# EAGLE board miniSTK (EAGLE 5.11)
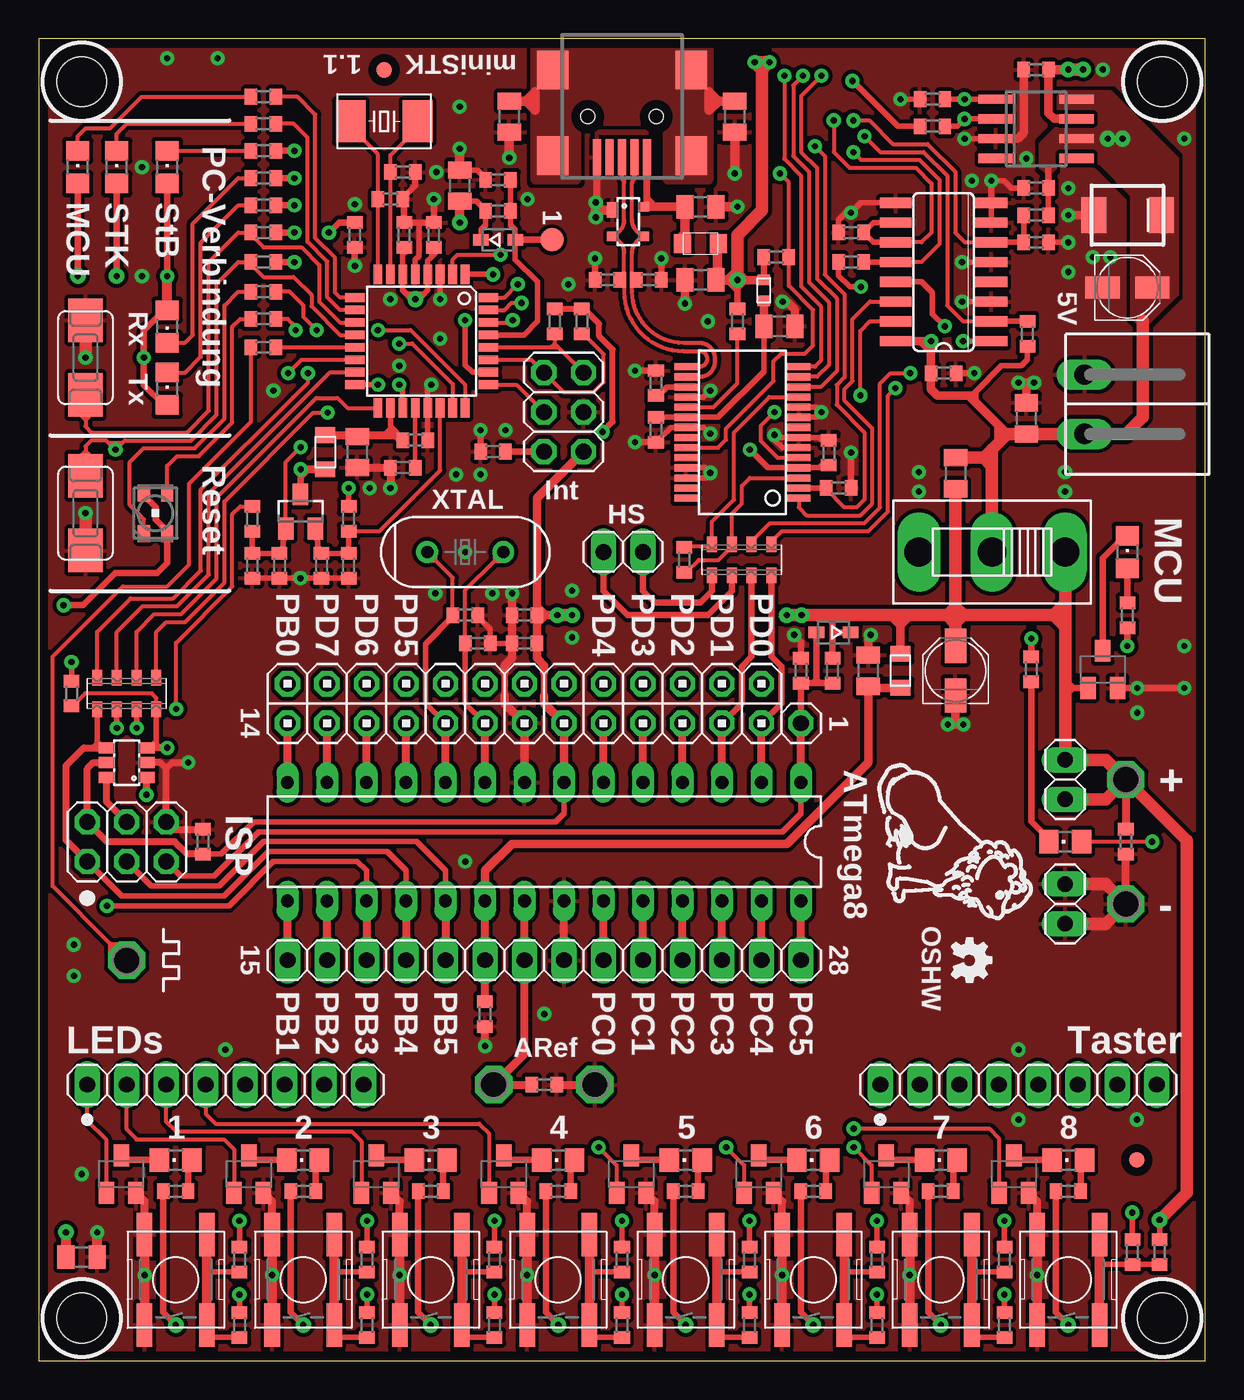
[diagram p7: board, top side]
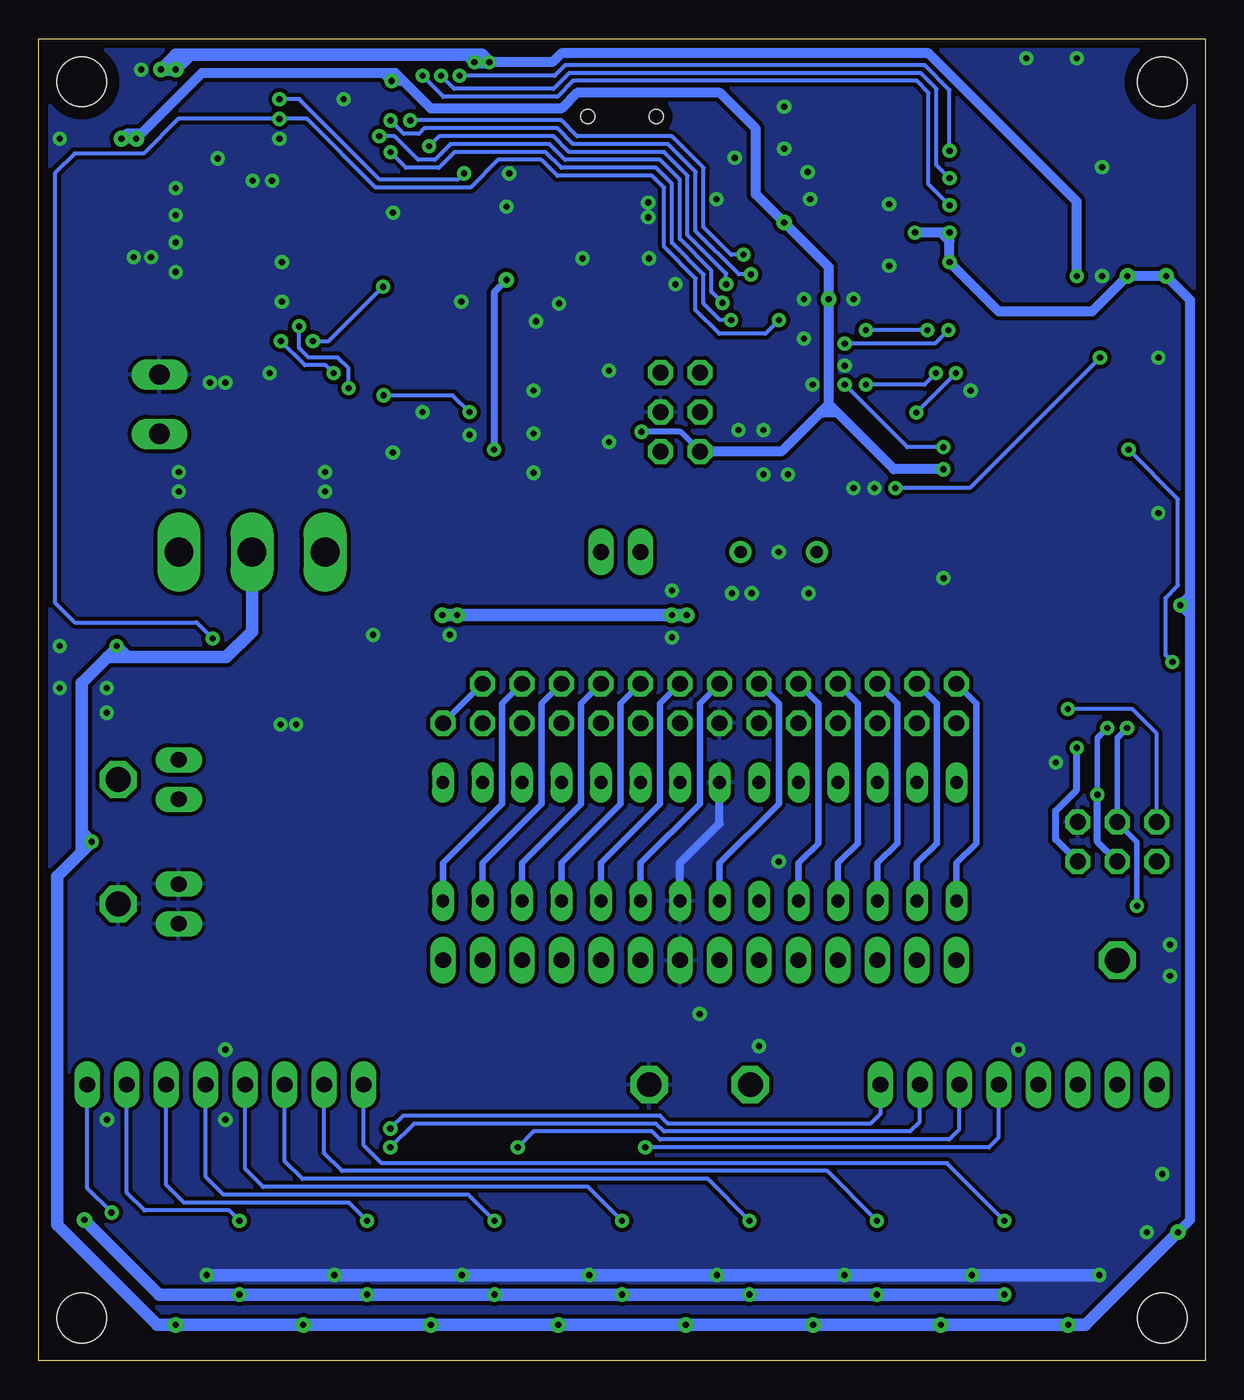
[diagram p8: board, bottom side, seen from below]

Size 75 x 85 mm. Coordinates in mm from the lower left corner, seen from the top.
Outline: 0,0 75,0 75,85 0,85 0,0
Copper layers (1*16): Top 0.035mm / dielectric 1.5mm / Bottom 0.035mm
Design rules "2-Layer 10x10 *": minimum track width 10mil, minimum drill 0.4mm, track to track 10mil, track to pad 10mil, pad to pad 10mil, via to via 10mil, smd to smd 10mil, copper to edge 0.6mm, drill to drill 10mil, minimum pad ring 12mil, minimum via ring 10mil, stop-mask expansion 4mil, vias tented up to drill 0.6mm, thermal gap 10mil
Net classes: 0 Standardleiter: width 0.254 mm, drill 0.4 mm; 1 USB Datenleitungen: width 0.254 mm; 2 IO-Schirm: clearance 0.5 mm; 3 Taktsignale: clearance 0.508 mm

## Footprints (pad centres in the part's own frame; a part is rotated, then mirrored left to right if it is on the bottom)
C-0603 = smd 0.8 x 1: 1 -0.8,0; 2 0.8,0
C-0805 = smd 1.1 x 1.5: 1 -1,0; 2 1,0
PANASONIC_B = smd 2.2 x 1.4: + 1.6,0; - -1.6,0
DIODE-SOD323 = smd 1 x 0.75: A 1.1,0; C -1.1,0
SOT23 = smd 1 x 1.4: 1 -0.95,-1.1; 2 0.95,-1.1; 3 0,1.1
SSOP28 = smd 0.46 x 1.5: 1 -4.225,-3.625; 2 -3.575,-3.625; 3 -2.925,-3.625; 4 -2.275,-3.625; 5 -1.625,-3.625; 6 -0.975,-3.625; 7 -0.325,-3.625; 8 0.325,-3.625; 9 0.975,-3.625; 10 1.625,-3.625; 11 2.275,-3.625; 12 2.925,-3.625; 13 3.575,-3.625; 14 4.225,-3.625; 15 4.225,3.625; 16 3.575,3.625; 17 2.925,3.625; 18 2.275,3.625; 19 1.625,3.625; 20 0.975,3.625; 21 0.325,3.625; 22 -0.325,3.625; 23 -0.975,3.625; 24 -1.625,3.625; 25 -2.275,3.625; 26 -2.925,3.625; 27 -3.575,3.625; 28 -4.225,3.625
SOIC8 = smd 0.6 x 2.2: 1 -1.905,-2.6; 2 -0.635,-2.6; 3 0.635,-2.6; 4 1.905,-2.6; 5 1.905,2.6; 6 0.635,2.6; 7 -0.635,2.6; 8 -1.905,2.6
SO16 = smd 0.66 x 2.032: 1 -4.445,-3.073; 2 -3.175,-3.073; 3 -1.905,-3.073; 4 -0.635,-3.073; 5 0.635,-3.073; 6 1.905,-3.073; 7 3.175,-3.073; 8 4.445,-3.073; 9 4.445,3.073; 10 3.175,3.073; 11 1.905,3.073; 12 0.635,3.073; 13 -0.635,3.073; 14 -1.905,3.073; 15 -3.175,3.073; 16 -4.445,3.073
TQFP32-08 = smd 1.27 x 0.559: 1 -4.293,2.8; 2 -4.293,2; 3 -4.293,1.2; 4 -4.293,0.4; 5 -4.293,-0.4; 6 -4.293,-1.2; 7 -4.293,-2; 8 -4.293,-2.8; 17 4.293,-2.8; 18 4.293,-2; 19 4.293,-1.2; 20 4.293,-0.4; 21 4.293,0.4; 22 4.293,1.2; 23 4.293,2; 24 4.293,2.8 | smd 0.559 x 1.27: 9 -2.8,-4.293; 10 -2,-4.293; 11 -1.2,-4.293; 12 -0.4,-4.293; 13 0.4,-4.293; 14 1.2,-4.293; 15 2,-4.293; 16 2.8,-4.293; 25 2.8,4.293; 26 2,4.293; 27 1.2,4.293; 28 0.4,4.293; 29 -0.4,4.293; 30 -1.2,4.293; 31 -2,4.293; 32 -2.8,4.293
1X02 = drill 1.016 long: 1 -1.27,0; 2 1.27,0
WE-CBF-0805 = smd 1.1 x 1.2: 1 -1.15,0; 2 1.15,0
BLM18 = smd 0.65 x 0.8: 1 -0.675,0; 2 0.675,0
BLM21 = smd 1 x 1.3: 1 -1.1,0; 2 1.1,0
CHIPLED-0805 = smd 1.25 x 1.5: A 1.05,0; C -1.05,0
OSRAM-TOPLED_2-S = smd 0.8 x 1.1: 1 -0.75,-1.3; 2 -0.75,1.3; 3 0.75,1.3; 4 0.75,-1.3
FIDUCIAL-1MM/CREAM = smd 1 x 1: FIDUCIAL 0,0
CRYSTAL-ABM7 = smd 1.9 x 2.7: 1 -2.15,0; 2 2.15,0
R-0603 = smd 0.8 x 1: 1 -0.8,0; 2 0.8,0
R-0805 = smd 1.1 x 1.5: 1 -1,0; 2 1,0
743C083 = smd 0.65 x 1: 1 -1.905,-1; 2 -0.635,-1; 3 0.635,-1; 4 1.905,-1; 5 1.905,1; 6 0.635,1; 7 -0.635,1; 8 -1.905,1
SWITCH-147873 = smd 2.8 x 2.2: P 2.4,0; S -2.4,0
TS-13-XX-X-C = drill 1.85 long: 1 -4.7,0; 2 0,0; 3 4.7,0
KSC-SW-J = smd 2.8 x 1: P1 -2.9,-2; P2 2.9,-2; S1 -2.9,2; S2 2.9,2
SC59-BEC = smd 1 x 1.4: B -0.95,-1.2; C 0,1.2; E 0.95,-1.2
TESTPOINT-1.6MM = drill 1.6 octagon: TP 0,0
TP15R = smd 1.5 x 1.5: TP 0,0
DO214-AA = smd 1.6 x 2.3: A 2.175,0; K -2.175,0
SOT143B = smd 1 x 0.7: 1 -0.75,-1 | smd 0.6 x 0.7: 2 0.95,-1; 3 0.95,1; 4 -0.95,1
SOT23-6_2 = smd 0.7 x 1: 1 -0.95,-1.3; 2 0,-1.3; 3 0.95,-1.3; 4 0.95,1.3; 5 0,1.3; 6 -0.95,1.3
MOUNT-DRILL_3.2 = hole 3.2: 0,0
31382102 = drill 1.3 long: 1 8,1.905; 2 8,-1.905
MINI-USB-B-SMD = smd 2.3 x 0.5: 1 7.85,1.6; 2 7.85,0.8; 3 7.85,0; 4 7.85,-0.8; 5 7.85,-1.6 | smd 2.5 x 2: S1 2.25,4.45; S2 7.75,4.45; S3 7.75,-4.45; S4 2.25,-4.45 | hole 0.9: 5.25,2.2; 5.25,-2.2
2X03 = drill 1.016 octagon: 1 -2.54,-1.27; 2 -2.54,1.27; 3 0,-1.27; 4 0,1.27; 5 2.54,-1.27; 6 2.54,1.27
1X01 = drill 1.016 octagon: 1 0,0
DIL28-3 = drill 0.813 long: 1 -16.51,-3.81; 2 -13.97,-3.81; 3 -11.43,-3.81; 4 -8.89,-3.81; 5 -6.35,-3.81; 6 -3.81,-3.81; 7 -1.27,-3.81; 8 1.27,-3.81; 9 3.81,-3.81; 10 6.35,-3.81; 11 8.89,-3.81; 12 11.43,-3.81; 13 13.97,-3.81; 14 16.51,-3.81; 15 16.51,3.81; 16 13.97,3.81; 17 11.43,3.81; 18 8.89,3.81; 19 6.35,3.81; 20 3.81,3.81; 21 1.27,3.81; 22 -1.27,3.81; 23 -3.81,3.81; 24 -6.35,3.81; 25 -8.89,3.81; 26 -11.43,3.81; 27 -13.97,3.81; 28 -16.51,3.81
1X14 = drill 1.016 long: 1 -16.51,0; 2 -13.97,0; 3 -11.43,0; 4 -8.89,0; 5 -6.35,0; 6 -3.81,0; 7 -1.27,0; 8 1.27,0; 9 3.81,0; 10 6.35,0; 11 8.89,0; 12 11.43,0; 13 13.97,0; 14 16.51,0
PQ_18_X = drill 0.8 round: 1 -2.45,0; 2 2.45,0
2X13 = drill 1.016 octagon: 1 -15.24,-1.27; 2 -15.24,1.27; 3 -12.7,-1.27; 4 -12.7,1.27; 5 -10.16,-1.27; 6 -10.16,1.27; 7 -7.62,-1.27; 8 -7.62,1.27; 9 -5.08,-1.27; 10 -5.08,1.27; 11 -2.54,-1.27; 12 -2.54,1.27; 13 0,-1.27; 14 0,1.27; 15 2.54,-1.27; 16 2.54,1.27; 17 5.08,-1.27; 18 5.08,1.27; 19 7.62,-1.27; 20 7.62,1.27; 21 10.16,-1.27; 22 10.16,1.27; 23 12.7,-1.27; 24 12.7,1.27; 25 15.24,-1.27; 26 15.24,1.27
1X08 = drill 1.016 long: 1 -8.89,0; 2 -6.35,0; 3 -3.81,0; 4 -1.27,0; 5 1.27,0; 6 3.81,0; 7 6.35,0; 8 8.89,0

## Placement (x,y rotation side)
C1  22pF  [C-0603]  28.22,46.13 0 top
C2  22pF  [C-0603]  27.42,47.94 0 top
C3  1µF  [C-0603]  10.56,33.37 90 top
C3.1  100nF  [C-0603]  58.18,63.5 0 top
C4  4,7µF  [C-0805]  53.34,44.37 90 top
C5  100nF  [C-0603]  31.23,46.13 180 top
C6  100nF  [C-0603]  28.69,22.29 270 top
C7  100nF  [C-0603]  32.5,17.75 0 top
C7.1  4,7µF  [C-0805]  2.75,6.67 0 top
C7.2  1µF  [C-0603]  69.9,33.37 270 top
C8  47nF  [C-0603]  49.01,44.37 90 top
C9  1µF  [C-0603]  20.32,72.39 270 top
C10  100nF  [C-0603]  39.69,59.87 270 top
C11  4,7µF  [C-0805]  27.07,75.56 90 top
C12  10nF  [C-0805]  42.55,74.2 0 top
C13  10nF  [C-0805]  30.25,80 270 top
C14  47pF  [C-0603]  39.23,69.5 0 top
C15  47pF  [C-0603]  36.57,69.5 180 top
C16  47nF  [C-0603]  29.53,75.93 180 top
C17  100nF  [C-0603]  39.69,62.87 90 top
C18  100nF  [C-0603]  50.8,58.39 90 top
C19  100nF  [C-0603]  64.14,83.03 180 top
C20  1µF  [C-0603]  64.14,75.41 180 top
C21  4,7µF  [C-0805]  42.55,69.5 180 top
C22  4,7µF  [C-0805]  47.62,66.52 0 top
C23  100nF  [C-0603]  23.41,57.42 180 top
C24  100nF  [C-0603]  23.5,72.39 90 top
C25  100nF  [C-0603]  25.4,72.39 90 top
C26  22pF  [C-0603]  23.41,76.44 0 top
C27  22pF  [C-0603]  22.61,74.69 0 top
C28  47nF  [C-0603]  18.18,51.12 270 top
C29  47nF  [C-0603]  15.48,51.12 270 top
C30  100nF  [C-0603]  24.21,59.2 0 top
C31  4,7µF  [C-0805]  20.48,58.42 270 top
C32  22µF  [PANASONIC_B]  58.95,44.37 90 top
C33  4,7µF  [C-0805]  63.5,60.59 90 top
C35  1µF  [C-0603]  31.23,47.94 180 top
C36  22µF  [PANASONIC_B]  70,69 0 top
C37  1µF  [C-0603]  29.21,58.46 180 top
D4.1  BAS16J  [DIODE-SOD323]  29.53,72.07 0 top
D4.2  BAT54C  [SOT23]  16.83,54.61 0 top
D6.1  BAS16J  [DIODE-SOD323]  51.11,46.83 180 top
IC2.1  FT232RL  [SSOP28]  45.24,59.69 90 top
IC2.2  MIC2025-2YM  [SOIC8]  64.14,79.22 270 top
IC3.1  74HC4053  [SO16]  58.18,70.01 90 top
IC4.1  ATmega88A-AU  [TQFP32-08]  24.61,65.56 270 top
JP1  RTS/CTS  [1X02]  37.58,52 0 top
L2.1  742792037  [WE-CBF-0805]  42.55,71.83 0 top
L2.2  BLM18PG121S  [BLM18]  46.62,68.83 90 top
L4.1  BLM21AH102S  [BLM21]  18.41,58.42 90 top
L6.1  BLM21AH102S  [BLM21]  55.4,44.37 270 top
LED7.1  LY R976  [CHIPLED-0805]  8.8,12.9 0 top
LED7.2  LY R976  [CHIPLED-0805]  17,12.9 0 top
LED7.3  LY R976  [CHIPLED-0805]  25.2,12.9 0 top
LED7.4  LY R976  [CHIPLED-0805]  33.4,12.9 0 top
LED7.5  LY R976  [CHIPLED-0805]  41.6,12.9 0 top
LED7.6  LY R976  [CHIPLED-0805]  49.8,12.9 0 top
LED7.7  LY R976  [CHIPLED-0805]  58,12.9 0 top
LED7.8  LY R976  [CHIPLED-0805]  66.2,12.9 0 top
LED9  LSG T676  [OSRAM-TOPLED_2-S]  7.5,54.5 0 top
LED10  LG R971  [CHIPLED-0805]  70,52 270 top
LED11  LG R971  [CHIPLED-0805]  2.5,76.75 270 top
LED12  LG R971  [CHIPLED-0805]  5,76.75 270 top
LED13  LS R976  [CHIPLED-0805]  8.25,76.75 270 top
LED14  LG R971  [CHIPLED-0805]  8.25,62.5 270 top
LED15  LG R971  [CHIPLED-0805]  8.25,66.5 90 top
LED16  LS R976  [CHIPLED-0805]  66,33.37 0 top
LOGO1.1  LOGO-10MM-TPLACE  [10MM-TPLACE]  59,33.37 270 top
LOGO1.2  OSHW-3MM-FILL-TSTOP  [OSHW-FILL-3MM-TSTOP]  57.75,36.25 90 bottom
LOGO1.3  OSHW-3MM-FILL-TPLACE  [OSHW-FILL-3MM-TPLACE]  60,25.75 270 top
MARK1  FIDUCIAL-1.0/CREAM  [FIDUCIAL-1MM/CREAM]  70.62,12.9 0 top
MARK2  FIDUCIAL-1.0/CREAM  [FIDUCIAL-1MM/CREAM]  22.21,83 0 top
P1.1  GF 4  [FOOT-12MM/REF]  7.5,73 0 top
P1.2  GF 4  [FOOT-12MM/REF]  67.5,73 0 top
P1.3  GF 4  [FOOT-12MM/REF]  12,7.5 0 top
P1.4  GF 4  [FOOT-12MM/REF]  63,7.5 0 top
Q4.1  14,7456MHz  [CRYSTAL-ABM7]  22.21,79.69 0 top
R1  330R  [R-0603]  12.9,6.5 270 top
R2  10k  [R-0603]  12.9,2.3 90 top
R3  330R  [R-0603]  21.1,6.5 270 top
R4  10k  [R-0603]  21.1,2.3 90 top
R5  330R  [R-0603]  29.3,6.5 270 top
R6  10k  [R-0603]  29.3,2.3 90 top
R7  330R  [R-0603]  37.5,6.5 270 top
R8  10k  [R-0603]  37.5,2.3 90 top
R9  330R  [R-0603]  45.7,6.5 270 top
R10  10k  [R-0603]  45.7,2.3 90 top
R11  330R  [R-0603]  53.9,6.5 270 top
R12  10k  [R-0603]  53.9,2.3 90 top
R13  330R  [R-0603]  62.1,6.5 270 top
R14  10k  [R-0603]  62.1,2.3 90 top
R15  330R  [R-0603]  70.33,6.99 270 top
R16  10k  [R-0603]  72.07,6.99 90 top
R17  330R  [R-0603]  8.8,10.9 180 top
R18  330R  [R-0603]  17,10.9 180 top
R19  330R  [R-0603]  25.2,10.9 180 top
R20  330R  [R-0603]  33.4,10.9 180 top
R21  330R  [R-0603]  41.6,10.9 180 top
R22  330R  [R-0603]  49.8,10.9 180 top
R23  330R  [R-0603]  58,10.9 180 top
R24  330R  [R-0603]  66.2,10.9 180 top
R25  10k  [R-0603]  51.04,44.37 90 top
R26  10k  [R-0603]  14.45,70.64 0 top
R27  1k  [R-0603]  44.93,66.83 90 top
R28  10k  [R-0603]  51.43,56.12 180 top
R29  1M  [R-0805]  44.75,80 270 top
R30  47k  [R-0603]  57.47,79.38 180 top
R31  10k  [R-0603]  47.42,70.96 180 top
R32  47k  [R-0603]  52.23,70.64 180 top
R33  47k  [R-0603]  63.58,66.03 270 top
R34  X  [R-0603]  64.14,73.66 0 top
R35  10k  [R-0603]  52.23,72.55 0 top
R36  10k  [R-0603]  14.45,72.55 0 top
R37  10k  [R-0603]  29.53,73.93 180 top
R38  X  [R-0805]  58.95,57.07 270 top
R39  X  [R-0603]  57.47,81.12 0 top
R40  47k  [R-0603]  19.92,54.13 90 top
R41  10k  [R-0603]  19.92,51.12 90 top
R42  10k  [R-0603]  13.73,51.12 90 top
R43  47k  [R-0603]  13.73,54.13 90 top
R44  47k  [R-0603]  34.92,66.83 90 top
R45  47k  [R-0603]  33.18,66.83 90 top
R46  330R  [R-0603]  70,47.94 270 top
R47  1,2k  [R-0603]  14.45,68.74 180 top
R48  560R  [R-0603]  14.45,66.99 180 top
R49  330R  [R-0603]  14.45,81.28 180 top
R50  330R  [R-0603]  14.45,79.53 180 top
R51  1,2k  [R-0603]  14.45,77.8 180 top
R52  330R  [R-0603]  14.45,74.3 180 top
R53  330R  [R-0603]  14.45,76.04 180 top
R54  1,2k  [R-0603]  63.82,44.45 270 top
R55  10k  [R-0603]  64.14,71.91 180 top
R56  X  [R-0603]  41.5,51.5 270 top
R57  47R  [R-0603]  14.45,65.16 180 top
R58  47R  [R-0603]  2.1,42.9 90 top
RN5.1  743C083271JP  [743C083]  45.2,51.5 0 top
RN5.2  743C083271JP  [743C083]  5.65,42.9 180 top
S5.1  147873-1  [SWITCH-147873]  3,54.5 270 top
S5.2  147873-1  [SWITCH-147873]  3,64.5 90 top
S6.1  TS-13-A12  [TS-13-XX-X-C]  61.3,52 180 top
S7.1  KSC222J  [KSC-SW-J]  8.8,5.2 270 top
S7.2  KSC222J  [KSC-SW-J]  17,5.2 270 top
S7.3  KSC222J  [KSC-SW-J]  25.2,5.2 270 top
S7.4  KSC222J  [KSC-SW-J]  33.4,5.2 270 top
S7.5  KSC222J  [KSC-SW-J]  41.6,5.2 270 top
S7.6  KSC222J  [KSC-SW-J]  49.8,5.2 270 top
S7.7  KSC222J  [KSC-SW-J]  58,5.2 270 top
S7.8  KSC222J  [KSC-SW-J]  66.2,5.2 270 top
T1  PDTC143ZT  [SC59-BEC]  5.3,12 0 top
T2  PDTC143ZT  [SC59-BEC]  13.5,12 0 top
T3  PDTC143ZT  [SC59-BEC]  21.7,12 0 top
T4  PDTC143ZT  [SC59-BEC]  29.9,12 0 top
T5  PDTC143ZT  [SC59-BEC]  38.1,12 0 top
T5.1  PDTC143ZT  [SC59-BEC]  68.42,44.45 0 top
T6  PDTC143ZT  [SC59-BEC]  46.3,12 0 top
T7  PDTC143ZT  [SC59-BEC]  54.5,12 0 top
T8  PDTC143ZT  [SC59-BEC]  62.7,12 0 top
TP1.1  5014  [TESTPOINT-1.6MM]  69.9,37.37 0 top
TP1.2  5011  [TESTPOINT-1.6MM]  69.9,29.37 0 top
TP1.3  5008  [TESTPOINT-1.6MM]  29.25,17.75 0 top
TP1.4  5006  [TESTPOINT-1.6MM]  35.75,17.75 0 top
TP1.5  5007  [TESTPOINT-1.6MM]  5.65,25.75 0 top
TP1.6  PTR1TP15R  [TP15R]  33,72.07 0 top
TVS1  SMBJ5V0A  [DO214-AA]  70.01,73.66 180 top
TVS2.1  PRTR5V0U2X  [SOT143B]  37.9,73.25 270 top
TVS5.1  SP3050-04HTG  [SOT23-6_2]  5.65,38.46 90 top
U$1  [MOUNT-DRILL_3.2]  2.75,2.75 0 top
U$2  [MOUNT-DRILL_3.2]  72.25,2.75 0 top
U$3  [MOUNT-DRILL_3.2]  72.25,82.25 0 top
U$4  [MOUNT-DRILL_3.2]  2.75,82.25 0 top
X1.1  31382102  [31382102]  75.25,61.5 180 top
X2.1  A-USBB-M5  [MINI-USB-B-SMD]  37.5,85.25 270 top
X5.1  Ext.  [2X03]  33.75,61 270 top
X6.1  Reset  [1X01]  49.01,40.99 0 top
X6.2  ATmega8  [DIL28-3]  32.5,33.37 180 top
X6.3  Ports  [1X14]  32.5,25.75 180 top
X6.4  ISP  [2X03]  5.65,33.37 0 top
X6.5  VCC  [1X02]  66,37.37 90 top
X6.6  GND  [1X02]  66,29.37 90 top
X6.7  PQ 18 G  [PQ_18_X]  27.42,52 180 top
X6.8  Ports  [2X13]  31.23,42.26 180 top
X7.1  Taster  [1X08]  63,17.75 0 top
X7.2  LEDs  [1X08]  12,17.75 0 top

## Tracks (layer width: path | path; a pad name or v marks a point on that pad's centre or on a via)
3V3OUT
  Top 0.356: IC2.1.17 40.39,62.62 39.84,62.06 C17.1
+5V  (via drill 0.4, 0.4 pad 1)
  Top 0.254: v71.6,33.37 LED16.A
  Top 0.356: 23.41,71.11 23.41,71.59 C24.1 | 23.41,71.11 IC4.1.6 23.41,68.83 23.65,68.58 | 23.41,71.11 23.65,71.36 | 25.24,70.96 25.72,71.44 | 25.24,70.96 25.01,70.73 IC4.1.4 25.01,68.83 24.44,68.26 v24.21,68.26 23.97,68.26 23.65,68.58 | 25.24,70.96 25.24,71.59 C25.1 | 23.65,68.58 24.77,68.58 | C11.1 28.15,74.56 28.73,73.98 R37.2 28.73,73.02 28.43,72.72 D4.1.C | R30.2 55.24,79.38 v52.32,82.3 | R34.2 C20.1 | R33.2 63.58,64.37 63.18,63.98 61.91,63.98 60.25,62.31 | 60.25,62.07 60.25,62.31 | 60.25,62.07 60.25,61.67 | 60.25,62.31 60.01,62.07 | 60.09,62.07 60.25,62.07 | R32.2 51.43,69.78 52.15,69.06 v52.86,69.06
  Top 0.381: R45.2 R44.2 35.08,67.63 36.04,66.67 36.04,65.88 36.89,65.02 36.89,60.37 v36.25,59.73
  Top 0.406: R17.2 8,3.1 v8.8,2.3 | R18.2 16.2,3.1 v17,2.3 | R19.2 24.4,3.1 v25.2,2.3 | R20.2 32.6,3.1 v33.4,2.3 | R21.2 40.8,3.1 v41.6,2.3 | R22.2 49,3.1 v49.8,2.3 | R23.2 57.2,3.1 v58,2.3 | R24.2 65.4,3.1 v66.2,2.3 | v5,69.75 LED12.A | v2.5,69.75 LED11.A | v16.43,72.55 R36.2 | v16.43,70.64 R26.2 | LED9.2 6.75,55.63 7.5,54.88 7.5,54.08 8.25,53.33 LED9.4 8.25,51.28 7.61,50.64 4.92,50.64 2.86,48.58 v1.59,48.58 | D4.2.3 16.83,56.83 | 16.83,56.83 v16.83,57.32 | 16.83,56.83 17.3,57.31 | v70,45.96 R46.2 | X5.1.5 C37.1 | C20.1 64.94,76.68 | C9.1 19.29,73.19 v18.65,72.55
  Top 0.508: v16.83,57.32 L4.1.1
  Top 0.559: 56.75,65.56 IC3.1.16 | 56.75,65.56 v57.38,65.56 57.38,64.94 | 57.38,64.94 C3.1.1 57.38,62.47 57.78,62.07 59.82,62.07 | 57.38,64.94 56.75,65.56 | 62.29,59.59 61.71,60.18 | 61.71,60.18 61.71,59.25 | 61.71,60.18 59.82,62.07 | 59.82,62.07 60.09,62.07
  Top 0.61: v27.07,73.18 C11.1
  Top 0.635: C7.1.1 v1.75,8.26
  Top 0.813: 71,66.87 71,60.68 69.91,59.59 X1.1.1 C33.1 62.29,59.59 61.3,58.6 | S6.1.2 61.3,57.53 | 61.3,57.53 61.3,58.6 | 61.3,58.6 60.77,58.07 | 60.77,58.07 R38.1 | 61.3,57.53 60.77,58.07
  Bottom 0.254: v52.86,69.06 56.36,65.56 v57.38,65.56
  Bottom 0.381: X5.1.5 33.75,59.73 v36.25,59.73
  Bottom 0.635: v16.83,57.32 20.01,57.32 23.65,60.96 | 23.65,60.96 24.21,61.51 | 24.21,61.51 v24.21,68.26 24.21,70.32 v27.07,73.18 28.89,75.01 28.89,79.22 31.21,81.53 40.39,81.53 41.4,80.52 49.78,80.52 52.07,82.8 52.83,82.8 | 16.43,71.99 v16.43,72.55 v18.65,72.55 | 0.95,49.21 0.95,68.2 v2.5,69.75 v5,69.75 7.28,67.47 13.26,67.47 v16.43,70.64 16.43,71.99 | 0.95,49.21 v1.59,48.58 0.95,47.94 | 0.95,47.94 0.95,49.21 | 0.95,47.94 0.95,9.05 v1.75,8.26 | 16.43,71.99 16.99,72.55 | 24.21,61.51 24.68,61.04 | 24.68,61.04 27.26,58.46 X5.1.5 | 24.68,61.04 24.59,60.96 23.65,60.96 | 51.56,82.3 v52.32,82.3 52.83,82.8 | 52.83,82.8 64.52,82.8 68.42,78.9 | 68.42,78.9 v68.74,78.58 v69.69,78.58 69.37,78.9 68.42,78.9
  Bottom 0.813: v1.75,8.26 7.7,2.3 v8.8,2.3 v17,2.3 v25.2,2.3 v33.4,2.3 v41.6,2.3 v49.8,2.3 v58,2.3 v66.2,2.3 67.39,2.3 73.82,8.73 73.82,31.15 v71.6,33.37 72.23,34.01 | 72.23,34.01 72.23,32.77 | 72.23,34.01 72.23,43.59 70.58,45.24 | 70.58,45.24 62.95,45.24 61.3,46.9 S6.1.2 | 70.58,45.24 70,45.82 v70,45.96 69.29,45.24
  pour Top (no thermals): 65.88,81.6 68.9,81.6 73.18,77.31 73.18,68.58 71.28,66.68 70.72,66.68 70.33,67.07 70.33,74.93 68.26,76.99 65.64,76.99 65.01,76.36 64.85,76.36 64.45,76.76 64.45,78.26 65.56,79.38 65.56,81.28
GND  (via drill 0.4)
  Top 0.356: C5.2 C1.2 29.02,47.05 28.22,47.84 C2.2 | 50.17,59.37 50.8,59.37 C18.2 | 50.17,59.37 IC2.1.7 47.47,59.37 v47.31,59.53 47.31,59.21 47.81,58.72 IC2.1.6 | 50.17,59.37 50.48,59.05 | IC4.1.5 24.21,70.8 24.45,71.04 24.45,73.19 | v25.81,68.26 IC4.1.3 | R41.1 C28.2 v16.82,50.32 C29.2 R42.1 | C30.2 IC4.1.21 25.01,62.53 v25.24,62.76 | C16.2 28.73,76.05 28.21,76.56 C11.2 | IC2.1.18 42.76,61.97 v43.18,62.39 | v43.18,59.61 42.78,60.02 IC2.1.21 40.65,60.02 C10.2 | IC2.1.25 42.85,57.41 v43.18,57.09 42.85,56.77 IC2.1.26 | IC2.1.10 50,61.31 v50.32,60.99 50,60.66 IC2.1.9 | v55.4,81.12 R39.1 | v59.37,70.64 IC3.1.5 | v59.37,68.1 IC3.1.3 | v59.53,78.58 IC2.2.3 | IC3.1.9 52.86,74.45 v52.23,73.82 51.91,73.82 51.43,73.34 R35.1 | R55.1 v66.2,71.91 | IC3.1.7 IC3.1.8 | C20.2 62.55,75.41 62.07,75.88 v61.26,75.88
  Top 0.406: C26.2 24.21,75.56 23.41,74.76 C27.2 23.5,74.69 C24.2 24.45,73.19 C25.2 v25.4,74.69 | C15.2 v35.77,70.88 | C14.2 v40.03,70.88 | T5.1.E v70.64,43.25 v73.66,43.25 | v20.32,70.41 C9.2 | C37.2 v28.41,59.85 | C10.2 v38.34,59.06 | C17.2 v38.34,63.66 | IC3.1.8 v61.26,75.88 | C3.1.2 v60.17,63.5 | R28.1 v52.23,58.39 | 29.96,42.78 29.96,44.28 | C8.2 49.01,46.24 v48.58,46.67
  Top 0.457: C3.2 8.66,34.17 X6.4.6 8.19,38.08 | TVS5.1.2 7.81,38.46 8.19,38.08 | X2.1.5 35.9,74.56 v35.81,74.48 | 8.19,38.08 8.57,38.46 v9.6,38.46
  Top 0.508: S7.8.P1 64.2,10.25 T8.E | S7.7.P1 56,10.25 T7.E | S7.6.P1 47.8,10.25 T6.E | S7.5.P1 39.6,10.25 T5.E | S7.4.P1 31.4,10.25 T4.E | S7.3.P1 23.2,10.25 T3.E | S7.2.P1 15,10.25 T2.E | S7.1.P1 6.8,10.25 T1.E | X6.3.7 X6.2.22 | C31.2 C23.2 v22.61,56.12 | TP1.2.TP C7.2.2 | C7.2 TP1.4.TP | v28.69,20.23 C6.2
  Top 0.559: v30.43,49.35 C35.2 C5.2 30.43,45.17 29.96,44.7 29.96,44.28 | v63,62.9 63.5,62.9 | 63.5,62.9 v64,62.9 | 58.95,40.92 v59.45,40.92 | 58.95,40.92 v58.45,40.92 | C19.2 63.34,78.96 62.95,78.58 IC2.2.3 | v41.55,67.98 C21.2 | C22.2 48.62,67.58 48.1,68.1 v47.83,68.1 | TVS1.A v66.2,73.66 | 63.5,62.9 C33.2 | C32.- 58.95,40.92 | 29.96,42.78 29.96,42.26 X6.8.14 X6.2.8 | C4.2 53.34,46.51 v53.5,46.67
  Top 0.61: S7.1.P2 v6.8,5.5 S7.1.P1 | S7.2.P2 v15,5.5 S7.2.P1 | S7.3.P2 v23.2,5.5 S7.3.P1 | S7.4.P2 v31.4,5.5 S7.4.P1 | S7.5.P2 v39.6,5.5 S7.5.P1 | S7.6.P2 v47.8,5.5 S7.6.P1 | S7.7.P2 v56,5.5 S7.7.P1 | S7.8.P2 v64.2,5.5 S7.8.P1 | v30.25,77.35 C13.2 | v44.75,76.35 R29.2 | 35.81,74 TVS2.1.1 | v35.81,73.52 35.81,74 | 35.81,74 v35.81,74.48 | C12.2 v44.93,74.2 | C11.2 v27.07,77.95
  Top 0.635: C7.1.2 v3.75,8.26
  Top 0.813: v3,64.5 S5.2.P | S5.1.P v3,54.5 | X6.6.2 68.63,30.64 TP1.2.TP 68.63,28.1 X6.6.1
  Bottom 0.508: X6.2.22 33.77,32 31.23,34.54 X6.2.8
  Bottom 0.813: v6.8,5.5 v15,5.5 v23.2,5.5 v31.4,5.5 v39.6,5.5 v47.8,5.5 v56,5.5 v64.2,5.5
  other vias: 21.27,56.12 31.42,74.69 22.61,68.26 23.18,63.98 6.62,69.75 27.42,52 6.62,76.75 15.08,62.39 2.75,12 8.25,83.75 11.5,83.75 27.07,80.64 20.32,74.37 25.56,76.44 27.42,32.09 32.5,22.29 28.41,56.99 26.83,56.99 30,59.85 43.02,66.83 34.29,49.53 2.25,26.75 2.25,24.75 56.6,55.88 66,55.88 66.2,75.41 68.42,83.03 67.79,70.96 68.9,70.96 73.66,45.95 66.2,70.01 70.64,41.66 66,57.15 56.6,57.15 34.29,46.51 60.01,75.88 63.5,77.31 25.81,65.72 34.05,69.22 70.62,15.5 63,15.5 63,20 12,20 29.16,49.35 25.5,49.35 73.66,78.58
  pour Bottom (rank 6): 0,85 75,85 75,0 0,0
  pour Top (rank 6): 0,85 75,85 75,0 0,0
  pour Top (rank 2, no thermals): 69.85,74.77 69.85,68.26 69.53,67.95 67.15,67.95 66.83,68.26 66.83,74.77 67.15,75.09 69.53,75.09
GNDIO
  Top 0.61: C13.1 31.31,81 | 31.31,81 31.91,81.6 31.91,80.41 31.32,81 31.31,81 | 43.7,81 R29.1 | 43.7,81 43.1,81.6 43.1,80.41 43.69,81 43.7,81
  pour Top (no thermals): 31.75,85 43.25,85 43.25,76 arc-90 43,75.75 40.5,75.75 arc-90 40.25,76 40.25,79.5 34.75,79.5 34.75,76 arc-90 34.5,75.75 32,75.75 arc-90 31.75,76
IC2.1/!RESET
  Top 0.254: IC2.1.19 43.38,61.31 44.93,62.87 R27.1
N$1
  Top 0.356: R16.1 R15.2 68.2,6.18 68.2,6.19
  Top 0.61: S7.8.S2 68.2,6.19 S7.8.S1
N$2
  Top 0.356: R14.1 60,1.5 S7.7.S2 | R13.2 60,5.7 60,6.35
  Top 0.61: S7.7.S2 60,6.35 S7.7.S1
N$3
  Top 0.356: R12.1 51.8,1.5 S7.6.S2 | R11.2 51.8,5.7 51.8,6.35
  Top 0.61: S7.6.S2 51.8,6.35 S7.6.S1
N$4
  Top 0.356: R10.1 43.6,1.5 S7.5.S2 | R9.2 43.6,5.7 43.6,6.35
  Top 0.61: S7.5.S2 43.6,6.35 S7.5.S1
N$5
  Top 0.356: R8.1 35.4,1.5 S7.4.S2 | R7.2 35.4,5.7 35.4,6.35
  Top 0.61: S7.4.S2 35.4,6.35 S7.4.S1
N$6
  Top 0.356: R6.1 27.2,1.5 S7.3.S2 | R5.2 27.2,5.7 27.2,6.35
  Top 0.61: S7.3.S2 27.2,6.35 S7.3.S1
N$7
  Top 0.356: R4.1 19,1.5 S7.2.S2 | R3.2 19,5.7 19,6.35
  Top 0.61: S7.2.S2 19,6.35 S7.2.S1
N$8
  Top 0.356: R2.1 10.8,1.5 S7.1.S2 | R1.2 10.8,5.7 10.8,6.35
  Top 0.61: S7.1.S2 10.8,6.35 S7.1.S1
N$9
  Top 0.406: R17.1 9.6,12.9 LED7.1.A
N$10
  Top 0.406: R18.1 17.8,12.9 LED7.2.A
N$11
  Top 0.406: R19.1 26,12.9 LED7.3.A
N$12
  Top 0.406: R20.1 34.2,12.9 LED7.4.A
N$13
  Top 0.406: R21.1 42.4,12.9 LED7.5.A
N$14
  Top 0.406: R22.1 50.6,12.9 LED7.6.A
N$15
  Top 0.406: R23.1 58.8,12.9 LED7.7.A
N$16
  Top 0.406: R24.1 67,12.9 LED7.8.A
N$17
  Top 0.406: LED7.8.C 62.7,12.9 T8.C
N$18
  Top 0.406: LED7.7.C 54.5,12.9 T7.C
N$19
  Top 0.406: LED7.6.C 46.3,12.9 T6.C
N$20
  Top 0.406: LED7.5.C 38.1,12.9 T5.C
N$21
  Top 0.406: LED7.4.C 29.9,12.9 T4.C
N$22
  Top 0.406: LED7.3.C 21.7,12.9 T3.C
N$23
  Top 0.406: LED7.2.C 13.5,12.9 T2.C
N$24
  Top 0.406: LED7.1.C 5.3,12.9 T1.C
N$25
  Top 0.457: 39.1,74.72 39.1,74.2 TVS2.1.4 | 39.1,74.72 X2.1.1 | 39.1,74.72 39.53,74.3
  Top 0.559: C12.1 TVS2.1.4
  Top 0.61: L2.1.1 41.55,71.83 41.55,72.5 | C12.1 41.55,72.53 41.55,72.5 | 41.55,72.5 41.2,72.15
N$28
  Top 0.254: IC4.1.7 C26.1 22.61,77.53 24.36,79.28 Q4.1.2
N$29
  Top 0.305: C23.1 IC4.1.20
N$30
  Top 0.254: IC4.1.8 C27.1 21.81,77.57 20.06,79.32 Q4.1.1
N$31
  Top 0.406: T5.1.C 68.42,51.62 69.85,53.05 LED10.C
N$32
  Top 0.406: R46.1 LED10.A
N$33
  Top 0.254: R53.2 12.83,76.04 9.91,73.12 9.91,65.96 9.4,65.45 LED15.C
N$34
  Top 0.254: LED14.C 9.4,63.55 10.41,64.57 10.41,71.88 12.83,74.3 R52.2
N$35
  Top 0.254: LED12.C 5,78.9 5.63,79.53 R50.2
N$36
  Top 0.254: LED11.C 2.5,78.74 3.01,79.25 4.57,79.25 6.6,81.28 R49.2
N$37
  Top 0.254: LED13.C R51.2
N$38
  Top 0.254: LED9.3 8.25,57.53 8.88,58.17 10.29,58.17 12.45,60.33 12.45,66.48 12.95,66.99 R48.2
N$39
  Top 0.254: LED9.1 6.75,54.12 5.85,55.02 5.85,57.78 6.74,58.67 10.03,58.67 11.94,60.58 11.94,67.85 12.83,68.74 R47.2
N$40
  Top 0.406: R54.2 63.82,34.66 64.95,33.54 LED16.C
PROG.!RESET
  Top 0.356: C16.1 R37.1 30.33,73.02 30.63,72.72 D4.1.A 30.63,70.81 32.07,69.37 32.07,66.83 31.2,65.96 IC4.1.29
  Top 0.406: D4.1.A TP1.6.TP
PROG.AVCC
  Top 0.356: 22.61,60.1 IC4.1.18 | 22.61,60.1 23.41,59.3 C30.1 | 22.61,60.1 22.61,59.91 22.23,59.53
  Top 0.508: L4.1.2 20.48,59.52 | 20.48,59.52 C31.1 | 20.48,59.52 22.95,59.52 23.28,59.2 C30.1
PROG.CLK
  Top 0.254: R57.1 IC4.1.13
PROG.CLK_OUT
  Top 0.254: 4.6,26.8 TP1.5.TP | 4.6,26.8 0.88,30.52 0.88,45.27 5.4,49.78 8.26,49.78 9.65,51.18 9.65,56.39 13.65,60.38 R57.2 | 4.6,26.8 5.2,26.8 4.6,26.2 4.6,26.8
PROG.EXT_GPIO
  Top 0.254: IC4.1.25 30.72,62.76 X5.1.3
PROG.EXT_SCL
  Top 0.254: IC4.1.28 33.4,65.16 | 33.4,65.16 X5.1.2 | 33.18,65.38 R45.1 | 33.4,65.16 33.18,65.38 | 33.18,65.38 33.16,65.38 32.94,65.17
PROG.EXT_SDA
  Top 0.254: IC4.1.27 31.66,64.36 X5.1.1 33.75,62.27 35.68,62.27 36.32,62.91 36.32,64.72 35.01,66.03 R44.1
PROG.LED_FAULT  (via drill 0.4)
  Top 0.356: IC2.2.2 v59.53,79.85 59.05,79.38 R30.1 | IC4.1.26 27.88,63.56 27.41,64.03 v27.41,66.91
  Top 0.406: v63.82,46.43 R54.1
  Bottom 0.254: v63.82,46.43 64.86,47.47 72.71,47.47 73.98,48.74 73.98,76.36 72.71,77.63 68.26,77.63 66.04,79.85 v59.53,79.85 57.75,79.85 53.34,75.44 47.24,75.44 45.47,77.22 42.67,77.22 41.66,76.2 35.56,76.2 34.8,75.44 34.8,71.63 32.77,69.6 32.77,67.56 31.24,66.04 28.28,66.04 v27.41,66.91
PROG.LED_STAT_GN  (via drill 0.4)
  Top 0.254: R48.1 16,66.99 16.51,66.48 v16.51,66.28 | IC4.1.23 26.61,62.8 24,65.41 v23.18,65.41
  Bottom 0.254: v23.18,65.41 17.38,65.41 v16.51,66.28
PROG.LED_STAT_RD  (via drill 0.4)
  Top 0.254: R47.1 16.13,68.74 17.02,67.85 17.02,67.12 v17.86,66.28 | IC4.1.24 27.41,62.76 23.89,66.28 v21.81,66.28
  Bottom 0.254: v17.86,66.28 v21.81,66.28
PROG.LED_UART_INT
  Top 0.254: IC4.1.10 19.37,67.56 18.54,68.39 18.54,70.67 17.27,71.94 17.27,78.64 16.38,79.53 R50.1
PROG.LED_UART_TG
  Top 0.254: R49.1 16.64,81.28 17.78,80.14 17.78,72.2 19.05,70.93 19.05,68.68 19.37,68.36 IC4.1.9
PROG.MISO  (via drill 0.4)
  Top 0.254: RN5.2.4 3.75,46.86 5.9,49.02 8.64,49.02 10.41,50.8 10.41,56.01 16.35,61.94 17.3,62.9 v17.3,63.5
  Top 0.356: v21.81,62.76 IC4.1.16
  Bottom 0.254: v17.3,63.5 18.04,62.76 v21.81,62.76
PROG.MOSI
  Top 0.254: RN5.2.3 5.01,46.86 6.67,48.51 8.89,48.51 10.92,50.55 10.92,55.75 18.73,63.56 IC4.1.15
PROG.RX  (via drill 0.4)
  Top 0.254: IC4.1.30 30.33,66.76 v30.48,66.91 | IC3.1.12 56.77,70.64 57.91,71.79 57.91,75.95 56.64,77.22 52.88,77.22 v52.39,77.71
  Top 0.356: IC3.1.12 R32.1
  Bottom 0.254: v30.48,66.91 31.19,66.91 32.26,67.98 32.26,69.85 34.29,71.88 34.29,75.69 35.31,76.71 41.4,76.71 42.42,77.72 48.26,77.72 49.28,76.71 51.39,76.71 v52.39,77.71
PROG.SCK
  Top 0.254: RN5.2.2 6.29,46.86 7.43,48.01 9.14,48.01 11.43,50.29 11.43,55.5 17.84,61.91 19.21,61.91 19.85,61.27 IC4.1.17
PROG.SW_RESET  (via drill 0.4)
  Top 0.254: 3,58.5 S5.1.S | IC4.1.12 19.37,65.96 17.53,67.81 17.53,68.55 16.38,69.69 14.45,69.69 13.65,70.49 R26.1 12.83,70.64 11.43,69.25 11.43,60.83 9.78,59.18 5.53,59.18 v4.92,58.58 4.46,59.04 | 3,58.5 3,58.8 3.38,59.18 4.32,59.18 4.46,59.04 | 4.46,59.04 5.38,59.04 5.4,59.05 | 3,58.5 2.5,58 3.5,58 3,58.5
  Top 0.356: R58.2 v2.1,44.93
  Bottom 0.254: v4.92,58.58 1.75,55.4 1.75,49.85 2.54,49.05 2.54,45.37 v2.1,44.93
PROG.SW_UART
  Top 0.254: 3,60.5 S5.2.S | 3,60.5 3,60.07 3.38,59.69 9.53,59.69 10.92,61.09 10.92,70.64 12.83,72.55 R36.1 13.65,72.4 14.45,71.6 16.89,71.6 18.03,70.45 18.03,68.1 19.37,66.76 IC4.1.11 | 3,60.5 3.5,61 2.5,61 3,60.5
PROG.TG_RESET  (via drill 0.4)
  Top 0.254: RN5.2.1 7.55,46.86 8.19,47.5 9.4,47.5 11.94,50.04 11.94,55.24 17.65,60.96 v18.57,60.96 | IC4.1.14 16.9,64.36 v16.03,63.5
  Bottom 0.254: v18.57,60.96 v16.03,63.5 | v18.57,60.96
PROG.TG_VCC_SENSE  (via drill 0.4)
  Top 0.254: D4.2.1 15.88,57.79 v16.83,58.74
  Top 0.356: R43.1 R42.2 C29.1 15.72,51.92 15.72,52.31 | D4.2.1 15.72,53.51 15.72,52.78 | 15.72,52.31 15.48,52.07 | 15.72,52.31 15.72,52.78 | 15.72,52.78 15.95,53.02 | IC4.1.19 23.41,62.53 v23.18,62.76
  Bottom 0.254: v16.83,58.74 19.15,58.74 v23.18,62.76
PROG.TX  (via drill 0.4)
  Top 0.254: IC4.1.31 29.94,67.56 30.4,68.03 v31.04,68.03 | IC3.1.2 59.44,66.83 58.42,67.85 58.42,76.2 56.9,77.72 54.12,77.72 v53.1,78.74
  Top 0.356: IC3.1.2 R33.1
  Bottom 0.254: v31.04,68.03 31.75,68.74 31.75,70.1 33.78,72.14 33.78,75.95 35.05,77.22 41.15,77.22 42.16,78.23 48.51,78.23 49.53,77.22 50.61,77.22 52.13,78.74 v53.1,78.74
PROG.VCCIO_SENSE
  Top 0.254: IC4.1.22 25.81,57.24 21.9,53.33 R40.1
  Top 0.356: R40.1 R41.2 C28.1 17.94,51.92 17.94,52.31 | D4.2.2 17.94,53.51 17.94,52.78 | 17.94,52.31 18.1,52.15 | 17.94,52.31 17.94,52.78 | 17.94,52.78 17.78,52.94
TG.!RESET  (via drill 0.4)
  Top 0.254: R58.1 2.18,42.1 2.98,42.9 7.26,42.9 7.55,42.61 RN5.2.8
  Top 0.356: 7.55,39.63 7.55,39.47 7.62,39.41 | 7.55,39.8 RN5.2.8 | 7.55,39.8 7.53,39.8 7.3,39.57 | 7.55,39.63 7.55,39.8 | 7.55,39.63 7.78,39.41 | X6.4.5 9.13,31.16 11.27,31.16 14.13,34.01 47.82,34.01 49.01,35.2 X6.2.1
  Top 0.406: X6.1.1 C8.1 50.01,43.57 | 50.01,43.57 R25.1 | 50.01,43.57 50.01,43.81 | 50.01,43.81 D6.1.A | 50.01,43.81 49.77,43.58 | 50.01,43.81 | 50.01,43.81 50.24,43.58
  Top 0.457: v8.26,39.41 7.62,39.41 TVS5.1.3
  Top 0.508: X6.2.1 X6.1.1
  Bottom 0.406: X6.1.1 X6.8.1
  Bottom 0.457: X6.4.5 9.6,33.51 9.6,35.36 8.26,36.71 v8.26,39.41
TG.AREF
  Top 0.508: X6.2.21 X6.3.8 31.23,19.73 TP1.3.TP C7.1
  Bottom 0.406: X6.2.21 31.23,32 27.42,35.81 27.42,42.26 X6.8.15
TG.AVCC
  Top 0.508: X6.2.20 X6.3.9 C6.1
  Top 0.559: X6.2.20 28.69,31.52 30.42,33.24 48.1,33.24 53.34,38.48 C4.1 53.34,43.27 L6.1.2
TG.LED_1
  Top 0.254: T1.B 4.35,14.19 3.11,15.43 X7.2.1
TG.LED_2
  Top 0.254: X7.2.2 5.65,14.86 6.29,14.22 11.91,14.22 12.55,13.59 T2.B
TG.LED_3
  Top 0.254: X7.2.3 8.19,15.37 8.82,14.73 20.11,14.73 20.75,14.1 T3.B
TG.LED_4
  Top 0.254: X7.2.4 10.73,15.88 11.37,15.24 28.32,15.24 28.95,14.61 T4.B
TG.LED_5  (via drill 0.4)
  Top 0.254: T5.B 37.15,12.57 v36,13.72
  Bottom 0.254: X7.2.5 13.27,14.35 13.9,13.72 v36,13.72
TG.LED_6  (via drill 0.4)
  Top 0.254: T6.B 45.35,12.57 v44.2,13.72
  Bottom 0.254: X7.2.6 15.81,14.86 16.45,14.22 35.05,14.22 35.56,14.73 43.18,14.73 v44.2,13.72
TG.LED_7  (via drill 0.4)
  Top 0.254: T7.B 53.55,12.57 v52.4,13.72
  Bottom 0.254: X7.2.7 18.35,15.37 18.98,14.73 34.8,14.73 35.31,15.24 50.88,15.24 v52.4,13.72
TG.LED_8  (via drill 0.4)
  Top 0.254: v52.4,14.92 61.12,14.92 61.75,14.29 T8.B
  Bottom 0.254: X7.2.8 20.89,15.88 21.52,15.24 34.54,15.24 35.05,15.75 51.58,15.75 v52.4,14.92
TG.PB0
  Top 0.508: X6.2.14 X6.8.26
TG.PB1
  Top 0.508: X6.3.14 X6.2.15
  Bottom 0.406: X6.2.15 15.99,32 14.72,33.27 14.72,42.26 X6.8.25
TG.PB2
  Top 0.508: X6.3.13 X6.2.16
  Bottom 0.406: X6.2.16 18.53,32 17.26,33.27 17.26,42.26 X6.8.23
TG.PB3  (via drill 0.4)
  Top 0.356: v5.01,40.68 RN5.2.6 | X6.2.17 21.07,31.52 20.48,32.11 15.08,32.11 12.22,29.25 v4.38,29.25
  Top 0.457: TVS5.1.6 4.35,35.94 X6.4.4
  Top 0.508: X6.2.17 X6.3.12
  Bottom 0.356: v5.01,40.68 5.65,40.05 X6.4.4 4.38,33.37 v4.38,29.25
  Bottom 0.406: X6.2.17 21.07,32 19.8,33.27 19.8,42.26 X6.8.21
TG.PB4
  Top 0.356: 3.75,39.66 3.75,39.5 3.65,39.41 | 3.75,39.79 RN5.2.5 | 3.75,39.79 3.97,39.57 | 3.75,39.66 3.75,39.79 | 3.75,39.66 3.49,39.41 | X6.2.18 23.61,31.52 22.38,32.74 14.76,32.74 11.91,29.89 5.33,29.89 X6.4.1
  Top 0.457: X6.4.1 1.75,33.46 1.75,38.26 2.89,39.41 3.65,39.41 TVS5.1.4
  Top 0.508: X6.2.18 X6.3.11
  Bottom 0.406: X6.2.18 23.61,32 22.34,33.27 22.34,42.26 X6.8.19
TG.PB5  (via drill 0.4)
  Top 0.356: v6.29,40.68 RN5.2.7 | X6.2.19 26.15,31.52 24.29,33.38 14.45,33.38 11.59,30.52 7.23,30.52 X6.4.3
  Top 0.457: TVS5.1.1 6.92,37.51 v6.92,36.39
  Top 0.508: X6.2.19 X6.3.10
  Bottom 0.356: v6.29,40.68 6.92,40.05 v6.92,36.39
  Bottom 0.406: X6.2.19 26.15,32 24.88,33.27 24.88,42.26 X6.8.17
  Bottom 0.457: v6.92,36.39 6.92,33.37 X6.4.3
TG.PB6
  Top 0.254: C1.1 27.42,49.55 29.33,51.46 | 29.34,51.47 X6.7.1 | 29.33,51.46 29.34,51.47 | 29.34,51.47 29.34,51.94 29.84,51.44 29.36,51.44 29.33,51.46
  Top 0.356: C1.1 27.42,42.26 X6.8.16
  Top 0.508: X6.2.9 X6.8.16
TG.PB7
  Top 0.254: 25.52,51.45 26.62,50.35 C2.1 | 25.52,51.45 X6.7.2 | 25.52,51.45 25.53,51.46 25.53,51.94 25.02,51.44 25.5,51.44 25.52,51.45
  Top 0.356: C2.1 26.62,47.84 24.88,46.1 24.88,42.26 X6.8.18
  Top 0.508: X6.2.10 X6.8.18
TG.PC0
  Top 0.508: X6.3.6 X6.2.23
  Bottom 0.406: X6.2.23 36.31,32 32.5,35.81 32.5,42.26 X6.8.13
TG.PC1
  Top 0.508: X6.3.5 X6.2.24
  Bottom 0.406: X6.2.24 38.85,32 35.04,35.81 35.04,42.26 X6.8.11
TG.PC2
  Top 0.508: X6.3.4 X6.2.25
  Bottom 0.406: X6.2.25 41.39,32 37.58,35.81 37.58,42.26 X6.8.9
TG.PC3
  Top 0.508: X6.3.3 X6.2.26
  Bottom 0.406: X6.2.26 43.93,32 40.12,35.81 40.12,42.26 X6.8.7
TG.PC4
  Top 0.508: X6.3.2 X6.2.27
  Bottom 0.406: X6.2.27 46.47,32 42.66,35.81 42.66,42.26 X6.8.5
TG.PC5
  Top 0.508: X6.3.1 X6.2.28
  Bottom 0.406: X6.2.28 49.01,32 45.2,35.81 45.2,42.26 X6.8.3
TG.PD0
  Top 0.406: X6.8.2 47.74,42.26 47.74,44.65 47.1,45.29 RN5.1.4
  Top 0.508: X6.2.2 X6.8.2
TG.PD1
  Top 0.406: X6.8.4 45.2,42.26 45.2,44.65 45.84,45.29 RN5.1.3
  Top 0.508: X6.2.3 X6.8.4
TG.PD2
  Top 0.508: X6.2.4 X6.8.6
TG.PD3
  Top 0.508: X6.2.5 X6.8.8
TG.PD4
  Top 0.508: X6.2.6 X6.8.10
TG.PD5
  Top 0.508: X6.2.11 X6.8.20
TG.PD6
  Top 0.508: X6.2.12 X6.8.22
TG.PD7
  Top 0.508: X6.2.13 X6.8.24
TG.SW_1  (via drill 0.4)
  Top 0.356: R1.1 v12.9,9
  Bottom 0.254: X7.1.1 54.11,13.84 52.97,12.7 16.6,12.7 v12.9,9
TG.SW_2  (via drill 0.4)
  Top 0.356: R3.1 v21.1,9
  Bottom 0.254: X7.1.2 56.65,13.34 55.51,12.19 24.29,12.19 v21.1,9
TG.SW_3  (via drill 0.4)
  Top 0.356: R5.1 v29.3,9
  Bottom 0.254: X7.1.3 59.19,12.83 58.05,11.68 31.98,11.68 v29.3,9
TG.SW_4  (via drill 0.4)
  Top 0.356: R7.1 v37.5,9
  Bottom 0.254: X7.1.4 61.73,12.32 60.59,11.18 39.68,11.18 v37.5,9
TG.SW_5  (via drill 0.4)
  Top 0.356: R9.1 v45.7,9
  Bottom 0.254: X7.1.5 64.27,11.81 63.13,10.67 47.37,10.67 v45.7,9
TG.SW_6  (via drill 0.4)
  Top 0.356: R11.1 v53.9,9
  Bottom 0.254: X7.1.6 66.81,11.3 65.67,10.16 55.06,10.16 v53.9,9
TG.SW_7  (via drill 0.4)
  Top 0.356: R13.1 v62.1,9
  Bottom 0.254: v62.1,9 62.75,9.65 68.21,9.65 69.35,10.79 X7.1.7
TG.SW_8  (via drill 0.4)
  Top 0.356: R15.1 v70.33,9.53
  Bottom 0.254: X7.1.8 71.89,11.09 v70.33,9.53
TG.VCC  (via drill 0.4, 0.4 pad 1)
  Top 0.254: v8.82,41.9 8.82,46.16 12.45,49.78 12.45,54.43 12.95,54.93 R43.2
  Top 0.356: R2.2 v12.9,4.25 | v21.1,4.25 R4.2 | v29.3,4.25 R6.2 | v37.5,4.25 R8.2 | v45.7,4.25 R10.2 | v53.9,4.25 R12.2 | v62.1,4.25 R14.2 | C3.1 11.73,32.57 13.81,34.65 33.21,34.65 33.77,35.2 X6.2.7 | v72.07,9.05 R16.2 | v72.07,9.05
  Top 0.406: 66.51,43.25 66.09,43.25 66,43.34 | 66.53,43.25 T5.1.B | 66.53,43.25 66.28,43.5 | 66.51,43.25 66.53,43.25 | 66.51,43.25 66.28,43.02 | 32.5,44.28 32.5,42.78 | 51.04,47.94 51.04,47.5 | 51.04,47.5 51.04,46.83 | 51.04,46.83 R25.2 | 51.04,46.83 51.28,46.83 | 51.28,46.83 D6.1.C | 51.28,46.83 | 51.28,46.83 51.12,46.99 | 51.28,46.83 51.12,46.67 | 51.04,47.5 51.07,47.5 51.36,47.78 | 51.04,47.5 51.01,47.5 50.72,47.78
  Top 0.457: C3.1 9.54,32.57 8.74,33.37 4.38,33.37 X6.4.2 3.11,38.08 3.49,38.46 TVS5.1.5
  Top 0.508: TP1.1.TP C7.2.1
  Top 0.559: C35.1 C5.1 32.03,45.17 32.5,44.7 32.5,44.28 | 55.4,47.94 55.4,47.31 | 55.4,47.31 L6.1.1 | 55.4,47.31 54.93,47.78 | 55.4,47.31 | 55.4,47.31 55.88,47.78 | 32.5,42.78 32.5,42.26 X6.8.12 X6.2.7 | 32.54,47.94 C35.1 | X5.1.6 32.03,55.47 C35.1 | v33.34,47.94 32.54,47.94 | 32.54,47.94 32.07,47.47 | 32.54,47.94 | 32.54,47.94 32.07,48.42
  Top 0.813: TP1.1.TP 73.82,33.45 73.82,10.79 v72.07,9.05 | TP1.1.TP 68.63,38.64 X6.5.2 66,43.34 66,47.94 | X6.5.1 68.63,36.1 TP1.1.TP | 66,47.94 S6.1.1 | 66,47.94 65.25,47.94 | 65.25,47.94 65.88,48.58 | 65.25,47.94 65.88,47.31 | 65.25,47.94 59.45,47.94 | 59.45,47.94 59.05,47.94 | 59.05,47.94 58.9,47.94 | 58.9,47.94 58.42,47.94 | 58.42,47.94 55.4,47.94 51.04,47.94 v48.1,47.94 | 58.95,47.44 58.95,47.84 59.05,47.94 | 58.95,47.41 C32.+ | 58.95,47.41 58.42,47.94 | 58.95,47.44 58.95,47.41 | 59.45,47.94 58.95,47.44 | 58.95,48.44 58.95,48 58.9,47.94 | 58.95,48.47 R38.2 | 58.95,48.47 58.42,47.94 | 58.95,48.44 58.95,48.47 | 59.45,47.94 58.95,48.44 | v34.29,47.94 v33.34,47.94
  Bottom 0.254: X6.4.2 3.11,40.32 4.69,41.9 v8.82,41.9
  Bottom 0.813: v12.9,4.25 v21.1,4.25 v29.3,4.25 v37.5,4.25 v45.7,4.25 v53.9,4.25 v62.1,4.25 67.27,4.25 v72.07,9.05 | v72.07,9.05 | v49.05,47.94 v48.1,47.94 v34.29,47.94 v33.34,47.94
UART.!EN  (via drill 0.4)
  Top 0.254: IC3.1.6 59.56,71.91 58.93,72.55 58.93,76.45 57.15,78.23 54.93,78.23 53.4,79.76 v52.39,79.76
  Top 0.356: IC4.1.1 v29.21,69.86 | IC3.1.6 R55.2 R34.1
  Bottom 0.254: v29.21,69.86 29.98,69.86 32.77,72.64 32.77,76.45 34.54,78.23 40.64,78.23 41.66,79.25 50.21,79.25 50.56,78.9 51.53,78.9 v52.39,79.76
UART.CTS
  Top 0.406: RN5.1.1 43.3,49.49 42.55,48.74 39.61,48.74 38.85,49.49 JP1.2
UART.RTS
  Top 0.406: RN5.1.2 44.56,49.49 43.02,47.94 37.86,47.94 36.31,49.49 JP1.1
UART.RX  (via drill 0.4)
  Top 0.254: v55.09,62.55 54.61,62.07 54.61,54.61 53.34,53.34 47.77,53.34 47.1,52.67 RN5.1.5
  Top 0.356: IC3.1.13 56.77,69.37 57.47,68.67 57.47,67.31 v58.26,66.52
  Bottom 0.254: v58.26,66.52 58.26,65.12 57.66,64.52 55.78,64.52 55.09,63.82 v55.09,62.55
UART.TG/!PROG  (via drill 0.4)
  Top 0.254: IC4.1.2 26.61,70.8 26.92,71.12 v29.69,71.12 | IC3.1.11 56.77,71.91 57.4,72.55 57.4,75.69 56.39,76.71 52.13,76.71 51.12,77.72 v51.12,79.76
  Top 0.356: IC3.1.10 53.66,73.18 R35.2 53.66,71.91 IC3.1.11
  Bottom 0.254: v29.69,71.12 30.48,71.12 32.26,72.9 32.26,76.71 34.29,78.74 40.39,78.74 41.4,79.76 v51.12,79.76
UART.TX  (via drill 0.4)
  Top 0.254: v56.04,63.5 54.77,63.5 54.1,62.83 54.1,54.86 53.09,53.85 47.01,53.85 45.84,52.67 RN5.1.6
  Top 0.356: v59.44,65.56 IC3.1.1
  Bottom 0.254: v59.44,65.56 57.88,64.01 56.55,64.01 v56.04,63.5
USB.!SLEEP  (via drill 0.4)
  Top 0.254: IC2.1.14 49.91,63.91 50.29,64.3 50.29,67.82 49.02,69.09 49.02,76.2 47.94,77.28 v47.94,82.63
  Top 0.406: R51.1 v16.43,77.8
  Bottom 0.254: v16.43,77.8 16.43,81.71 18.03,83.31 41.15,83.31 41.83,82.63 v47.94,82.63
USB.!VCC_EN  (via drill 0.4)
  Top 0.254: IC2.1.23 43.69,58.72 44.2,59.22 44.2,59.94 47.24,62.99 47.24,64.26 47.75,64.77 49.28,64.77 49.78,65.28 49.78,67.56 48.23,69.12 R31.1 48.23,75.78 v47.65,76.35
  Top 0.356: IC2.2.1 v59.53,81.12 R39.2
  Bottom 0.254: v47.65,76.35 48.05,75.95 53.09,75.95 R39.2 v59.53,81.12
USB.CTS_TTL
  Top 0.254: IC2.1.11 46.98,61.97 44.7,59.69 44.7,55.37 43.3,53.96 RN5.1.8 43.3,52.4 41.5,52.4 R56.1
USB.DMU
  Top 0.254: 38.79,72.3 38.45,71.96 arc45 38.15,71.25 38.15,69.5 | 38.79,72.3 TVS2.1.3 | 38.79,72.3 38.45,72.64 arc-45 38.15,73.35 38.15,75.75 arc-45 38.23,75.93 arc45 38.3,76.1 X2.1.2 | 38.15,69.5 C14.1 | 38.15,69.5 38.15,68.75 arc90 41.46,65.44 42.48,65.44 arc-90 43.5,64.43 43.5,64.28 arc-90 42.48,63.27 IC2.1.16
USB.DPU
  Top 0.254: 37.01,72.3 37.35,71.96 arc-45 37.65,71.25 37.65,69.5 | 37.01,72.3 TVS2.1.2 | 37.01,72.3 37.35,72.64 arc45 37.65,73.35 37.65,75.75 arc45 37.57,75.93 arc-45 37.5,76.1 X2.1.3 | C15.1 37.65,69.5 | 37.65,69.5 37.65,68.71 arc90 41.42,64.93 42.48,64.93 arc-90 42.98,64.42 arc-90 42.48,63.91 IC2.1.15
USB.DTR_TTL  (via drill 0.4)
  Top 0.254: IC4.1.32 29.95,68.36 v30.8,69.22 | R28.2 50.63,56.05 51.82,54.86 52.58,54.86 53.09,55.37 53.09,59.69 51.31,61.47 51.31,62.74 51.82,63.25 51.82,68.58 50.55,69.85 50.55,77.47 v49.91,78.11
  Top 0.356: R28.2 IC2.1.2
  Bottom 0.254: v30.8,69.22 30.8,69.91 33.27,72.39 33.27,76.2 34.8,77.72 40.89,77.72 41.91,78.74 49.28,78.74 v49.91,78.11
USB.LED_RX  (via drill 0.4)
  Top 0.254: IC2.1.13 50.04,63.27 50.8,64.03 50.8,68.07 49.53,69.34 49.53,76.45 48.51,77.47 48.51,82.01 v49.13,82.63
  Top 0.406: R53.1 v16.43,76.04
  Bottom 0.254: v16.43,76.04 17.27,76.88 17.27,81.79 18.29,82.8 40.89,82.8 41.91,81.79 48.29,81.79 v49.13,82.63
USB.LED_TX  (via drill 0.4)
  Top 0.254: IC2.1.12 50.29,62.62 51.31,63.63 51.31,68.33 50.04,69.6 50.04,76.71 49.02,77.72 49.02,81.33 v50.32,82.63
  Top 0.406: R52.1 v16.43,74.3
  Bottom 0.254: v16.43,74.3 17.78,75.64 17.78,81.53 18.54,82.3 40.64,82.3 41.66,81.28 48.97,81.28 v50.32,82.63
USB.RTS_TTL
  Top 0.254: IC2.1.3 45.72,56.77 45.21,56.26 45.21,55.12 44.56,54.47 RN5.1.7 44.56,52.36 43.71,51.5 42.44,51.5 41.64,50.7 R56.2
USB.RX_TTL  (via drill 0.4)
  Top 0.254: IC2.1.5 47.5,58.06 46.99,58.58 46.43,59.13 46.43,60.12 v47.31,60.99 | IC3.1.15 53.45,66.83 52.83,66.22 v52.83,62.07
  Bottom 0.254: v52.83,62.07 48.39,62.07 v47.31,60.99
USB.TX_TTL
  Top 0.254: IC2.1.1 48.87,54.86 49.38,54.36 52.83,54.36 53.59,55.12 53.59,59.94 51.82,61.72 51.82,62.48 52.32,62.99 52.32,66.98 53.45,68.1 IC3.1.14
USB.VCC
  Top 0.356: C10.1 IC2.1.20 43.68,60.66 46.62,63.61 C22.1
  Top 0.559: C22.1 L2.2.1
VCCIO  (via drill 0.4, 0.4 pad 1)
  Top 0.356: 50.19,57.41 50.8,57.41 C18.1 | 50.19,57.41 IC2.1.4 46.88,57.41 v45.72,58.58 | 50.19,57.41 50.48,57.71 | v19.92,56.12 R40.2
  Top 0.406: v8.25,69.75 LED13.A | LED15.A 8.05,67.55 6.75,66.25 v6.75,64.5 6.75,62.75 8.05,61.45 LED14.A | v44.93,69.5 44.93,68.98 | 44.93,68.82 R27.2 | 44.93,68.82 44.29,69.45 | 44.93,68.98 44.93,68.82 | 44.93,68.98 45.4,69.45 | 44.21,69.53 44.93,70.25 44.93,70.09 45.48,69.53 | L2.2.2 R31.2
  Top 0.559: C19.1 64.94,80.23 65.32,79.85 IC2.2.7 | v44.93,69.5 L2.2.2
  Top 0.61: 43.66,69.5 C21.1 | 43.66,69.5 43.66,71.83 L2.1.2 | v44.93,69.5 43.66,69.5 | v66.2,83.03 C19.1
  Top 0.635: LED15.A v8.25,69.75
  Top 0.813: 46.51,83.03 v46.99,83.5 v46.04,83.5 46.51,83.03 | 46.51,83.03 | 46.51,83.03 46.51,73.98 44.93,72.39 44.93,70.25 v44.93,69.5 | v66.2,83.03 v67.15,83.03
  Bottom 0.254: v19.92,56.12 15.13,56.12 v6.75,64.5
  Bottom 0.457: v45.72,58.58 45.72,68.71 v44.93,69.5
  Bottom 0.635: v8.25,69.75 8.25,74.54 17.78,84.07 41.4,84.07 41.97,83.5 v46.04,83.5
  Bottom 0.813: 47.47,83.98 v46.99,83.5 v46.04,83.5 46.51,83.98 47.47,83.98 | 47.47,83.98 65.25,83.98 | 65.25,83.98 v66.2,83.03 v67.15,83.03 66.2,83.98 65.25,83.98

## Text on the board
tNames: 1.1 | miniSTK | PC-Verbindung | MCU | STK | StB | 1 | 5V | Rx | Tx | Reset | XTAL | Int | HS | MCU | PB0 | PD7 | PD6 | PD5 | PD4 | PD3 | PD2 | PD1 | PD0 | 14 | 1 | ATmega8 | + | ISP | OSHW | - | 15 | 28 | PB1 | PB2 | PB3 | PB4 | PB5 | PC0 | PC1 | PC2 | PC3 | PC4 | PC5 | Taster | LEDs | ARef | 1 | 2 | 3 | 4 | 5 | 6 | 7 | 8
bStop: OSHW | CC-BY-SA 3.0 | www.leo-andres.de | PCB V1.1 | 07/2013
